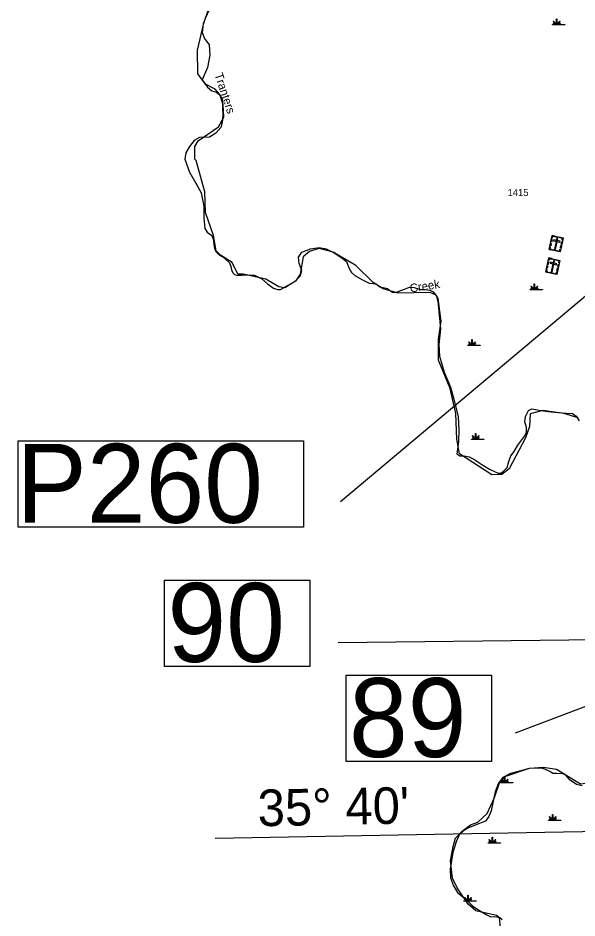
# Model space of a CAD drawing. Extents: x 2532689 to 2764727, y 536648 to 732970.
# Drawn here: x 2532689 to 2542603, y 701027 to 716987 of the extents above; entities that cross this region are included whole.
import ezdxf

# ---------------------------------------------------------------- set-up
doc = ezdxf.new("R2010")
doc.units = 0
for name, color, linetype in [('Exist Boundary Political CountyLine', 7, 'Continuous'), ('Exist Cultural Cemetery CELL', 7, 'Continuous'), ('Exist Hydrographic Creek Single Shore', 7, 'Continuous'), ('Exist Hydrographic Creek Single Shore Label', 7, 'Continuous'), ('Exist Hydrographic Swamp CELL', 7, 'Continuous'), ('Exist Road Secondary Structure Pipe Number Label', 7, 'Continuous'), ('Exist Road Secondary Structure Standard Bridge Number Label', 7, 'Continuous'), ('Exist Road Secondary Type 51 Number Label', 7, 'Continuous'), ('Map Preparation Longitude Latitude Label', 7, 'Continuous'), ('Map Preparation Longitude Latitude Lines', 7, 'Continuous')]:
    doc.layers.add(name, color=color, linetype=linetype)

msp = doc.modelspace()

# ---------------------------------------------------------------- linework, layer by layer
at = {"layer": 'Exist Boundary Political CountyLine'}
for points in [[(2536109, 717196), (2536014, 716987), (2535975, 716882), (2535955, 716728), (2535999, 716625), (2536079, 716511), (2536089, 716326), (2536049, 716112), (2535955, 715892)], [(2535955, 715892), (2536049, 715760), (2536129, 715695), (2536209, 715670), (2536274, 715620), (2536308, 715541), (2536318, 715406), (2536323, 715261), (2536308, 715132), (2536284, 715047), (2536199, 714942), (2536084, 714872), (2535905, 714870), (2535815, 714815), (2535730, 714710), (2535666, 714596), (2535646, 714486), (2535730, 714252), (2535840, 714057), (2535940, 713885), (2535985, 713651), (2535985, 713446), (2536004, 713254), (2536044, 713189), (2536129, 713130), (2536154, 713050), (2536164, 712970), (2536174, 712905), (2536199, 712845), (2536264, 712780), (2536343, 712736), (2536438, 712648), (2536463, 712578), (2536478, 712519), (2536498, 712469), (2536528, 712439), (2536578, 712429), (2536662, 712429), (2536797, 712434), (2536886, 712429), (2537011, 712359), (2537111, 712274), (2537220, 712194), (2537290, 712175), (2537345, 712172), (2537479, 712252), (2537604, 712322), (2537694, 712411), (2537724, 712511), (2537674, 712631), (2537664, 712743), (2537724, 712833), (2537878, 712893), (2538028, 712918), (2538152, 712893), (2538297, 712823), (2538441, 712728), (2538516, 712668), (2538556, 712559), (2538606, 712474), (2538665, 712419), (2538800, 712344), (2538915, 712282), (2539039, 712272), (2539109, 712222), (2539164, 712207), (2539244, 712192), (2539303, 712142), (2539333, 712127), (2539388, 712122), (2539458, 712147), (2539543, 712177), (2539632, 712212), (2539717, 712207), (2539792, 712187), (2539847, 712172), (2539911, 712172), (2539991, 712162), (2540051, 712132), (2540111, 712057), (2540136, 711963), (2540141, 711908), (2540180, 711476), (2540150, 711197), (2540165, 710988), (2540250, 710706), (2540360, 710442), (2540420, 710227), (2540494, 709913), (2540509, 709686), (2540499, 709472), (2540474, 709257), (2540524, 709222), (2540604, 709222), (2540689, 709207), (2540773, 709162), (2540913, 709068), (2541052, 708988), (2541207, 708913), (2541252, 708918), (2541302, 708953)], [(2541302, 708953), (2541366, 709018), (2541396, 709123), (2541431, 709222), (2541486, 709302), (2541551, 709412), (2541626, 709507), (2541680, 709576), (2541705, 709641), (2541705, 709731), (2541680, 709821), (2541690, 709920), (2541745, 710025), (2541800, 710058), (2541969, 710028), (2542084, 710008), (2542268, 709993), (2542418, 709978), (2542522, 709973), (2542587, 709925), (2542642, 709846)], [(2542592, 703393), (2542483, 703472), (2542403, 703557), (2542353, 703582), (2542243, 703592), (2542174, 703587), (2542124, 703627), (2542034, 703667), (2541969, 703682), (2541860, 703682), (2541755, 703677), (2541586, 703632), (2541426, 703587), (2541287, 703517), (2541212, 703418), (2541152, 703263), (2541117, 703098), (2541082, 702929), (2541042, 702829), (2540978, 702744), (2540798, 702674), (2540664, 702620), (2540589, 702575), (2540514, 702500), (2540459, 702380), (2540400, 702186), (2540355, 701892), (2540360, 701742), (2540410, 701597), (2540484, 701478), (2540644, 701348), (2540758, 701238), (2540873, 701158), (2540993, 701091), (2541072, 701046), (2541147, 701051), (2541237, 701036), (2541277, 701001)], [(2542692, 703370), (2542592, 703393)]]:
    msp.add_lwpolyline(points, dxfattribs=at)
at = {"layer": 'Exist Cultural Cemetery CELL'}
for points in [[(2542165, 713131), (2542359, 713087), (2542304, 712839), (2542109, 712882)], [(2542156, 713088), (2542167, 713086), (2542174, 713117), (2542213, 713109), (2542216, 713119), (2542165, 713131)], [(2542237, 713115), (2542288, 713103), (2542285, 713092), (2542235, 713103)], [(2542350, 713045), (2542339, 713047), (2542346, 713079), (2542306, 713088), (2542309, 713098), (2542359, 713087)], [(2542125, 712950), (2542134, 712993), (2542145, 712990), (2542136, 712948)], [(2542139, 713016), (2542149, 713058), (2542160, 713056), (2542150, 713014)], [(2542190, 713055), (2542186, 713037), (2542301, 713011), (2542305, 713030)], [(2542265, 713078), (2542247, 713082), (2542203, 712884), (2542221, 712880)], [(2542308, 712912), (2542318, 712954), (2542329, 712952), (2542320, 712909)], [(2542323, 712976), (2542332, 713018), (2542343, 713016), (2542334, 712974)], [(2542142, 712875), (2542144, 712886), (2542123, 712891), (2542132, 712931), (2542121, 712933), (2542109, 712882)], [(2542168, 712881), (2542251, 712862), (2542248, 712851), (2542166, 712870)], [(2542271, 712846), (2542274, 712857), (2542295, 712852), (2542304, 712892), (2542315, 712889), (2542304, 712839)], [(2542104, 712731), (2542299, 712687), (2542243, 712439), (2542049, 712482)], [(2542079, 712616), (2542088, 712659), (2542099, 712656), (2542090, 712614)], [(2542095, 712689), (2542106, 712686), (2542113, 712718), (2542153, 712709), (2542155, 712720), (2542104, 712731)], [(2542129, 712656), (2542125, 712637), (2542240, 712612), (2542244, 712630)], [(2542204, 712679), (2542186, 712683), (2542142, 712485), (2542160, 712481)], [(2542177, 712715), (2542227, 712703), (2542225, 712692), (2542174, 712704)], [(2542289, 712645), (2542278, 712648), (2542285, 712679), (2542246, 712688), (2542248, 712699), (2542299, 712687)], [(2542081, 712475), (2542083, 712487), (2542062, 712491), (2542071, 712531), (2542060, 712533), (2542049, 712483)], [(2542064, 712551), (2542073, 712593), (2542085, 712591), (2542075, 712548)], [(2542107, 712481), (2542190, 712463), (2542188, 712451), (2542105, 712470)], [(2542211, 712446), (2542213, 712457), (2542235, 712453), (2542243, 712492), (2542254, 712490), (2542243, 712439)], [(2542248, 712512), (2542257, 712554), (2542268, 712552), (2542259, 712509)], [(2542262, 712576), (2542272, 712619), (2542283, 712616), (2542273, 712574)]]:
    msp.add_lwpolyline(points, close=True, dxfattribs=at)
at = {"layer": 'Exist Hydrographic Creek Single Shore'}
for points in [[(2536585, 712446), (2536490, 712652), (2536279, 712781), (2536202, 712857), (2536156, 713131), (2536015, 713536), (2536000, 713903), (2535848, 714458), (2535823, 714483), (2535827, 714707), (2535883, 714807), (2536246, 715055), (2536342, 715227), (2536330, 715449), (2536268, 715631), (2536183, 715722), (2536015, 715811), (2535878, 715999), (2535871, 716416), (2535987, 716893), (2536074, 717153)], [(2542623, 709897), (2542372, 709976), (2541996, 710029), (2541772, 709968), (2541759, 709741), (2541688, 709541), (2541398, 708994), (2541267, 708890), (2541092, 708886), (2540518, 709260), (2540472, 709518), (2540455, 709976), (2540355, 710416), (2540146, 710919), (2540148, 711294), (2540192, 711611), (2540143, 712012), (2540108, 712070), (2539999, 712118), (2539433, 712105), (2539165, 712186), (2538988, 712297), (2538682, 712600), (2538278, 712836), (2538027, 712898), (2537861, 712846), (2537746, 712752), (2537693, 712442), (2537612, 712323), (2537423, 712204), (2537314, 712219), (2537087, 712355), (2536685, 712447), (2536585, 712446)], [(2540714, 702679), (2540846, 702724), (2541010, 702878), (2541138, 703163), (2541233, 703439), (2541339, 703542), (2541762, 703683), (2542003, 703703), (2542237, 703667), (2542667, 703408), (2542908, 703438), (2543220, 703693), (2543385, 703769), (2543949, 703913), (2544031, 703999), (2544061, 704167)], [(2541266, 700699), (2541227, 701032), (2541176, 701073), (2540808, 701156), (2540672, 701272), (2540476, 701560), (2540397, 701734), (2540359, 702041), (2540404, 702292), (2540451, 702442), (2540566, 702568), (2540714, 702679)]]:
    msp.add_lwpolyline(points, dxfattribs=at)
at = {"layer": 'Exist Hydrographic Swamp CELL'}
for points in [[(2542169, 716871), (2542222, 716871), (2542224, 716875), (2542186, 716890), (2542189, 716895), (2542226, 716879), (2542228, 716882), (2542183, 716927), (2542189, 716932), (2542234, 716886), (2542240, 716889), (2542240, 716972), (2542247, 716972), (2542247, 716889), (2542254, 716886), (2542299, 716932), (2542304, 716927), (2542260, 716882), (2542262, 716878), (2542303, 716897), (2542305, 716892), (2542264, 716874), (2542266, 716871), (2542387, 716871), (2542387, 716864), (2542169, 716864)], [(2541772, 712171), (2541825, 712172), (2541827, 712175), (2541789, 712190), (2541791, 712195), (2541829, 712179), (2541831, 712182), (2541786, 712227), (2541791, 712232), (2541837, 712187), (2541843, 712189), (2541843, 712272), (2541850, 712272), (2541850, 712189), (2541857, 712187), (2541902, 712232), (2541907, 712227), (2541863, 712182), (2541865, 712179), (2541906, 712197), (2541908, 712192), (2541867, 712174), (2541869, 712172), (2541990, 712171), (2541990, 712164), (2541772, 712164)], [(2540667, 711187), (2540720, 711187), (2540722, 711190), (2540684, 711205), (2540686, 711210), (2540724, 711195), (2540726, 711197), (2540681, 711242), (2540687, 711247), (2540732, 711202), (2540738, 711204), (2540738, 711287), (2540745, 711287), (2540745, 711204), (2540752, 711202), (2540797, 711247), (2540802, 711242), (2540758, 711197), (2540760, 711194), (2540801, 711212), (2540803, 711207), (2540762, 711190), (2540764, 711187), (2540885, 711187), (2540885, 711180), (2540667, 711180)], [(2540730, 709521), (2540783, 709521), (2540785, 709524), (2540747, 709539), (2540750, 709544), (2540787, 709529), (2540789, 709532), (2540745, 709576), (2540750, 709581), (2540795, 709536), (2540801, 709538), (2540801, 709621), (2540809, 709621), (2540809, 709538), (2540815, 709536), (2540860, 709581), (2540865, 709576), (2540821, 709532), (2540823, 709528), (2540864, 709547), (2540866, 709542), (2540825, 709524), (2540827, 709521), (2540948, 709521), (2540948, 709514), (2540730, 709514)], [(2541245, 703430), (2541298, 703430), (2541300, 703433), (2541262, 703448), (2541265, 703453), (2541302, 703438), (2541304, 703441), (2541259, 703485), (2541265, 703490), (2541310, 703445), (2541316, 703447), (2541316, 703530), (2541323, 703530), (2541323, 703447), (2541330, 703445), (2541375, 703490), (2541380, 703485), (2541336, 703441), (2541338, 703437), (2541379, 703456), (2541381, 703450), (2541340, 703433), (2541342, 703430), (2541463, 703430), (2541463, 703423), (2541245, 703423)], [(2542099, 702764), (2542151, 702764), (2542153, 702768), (2542115, 702782), (2542118, 702788), (2542156, 702772), (2542157, 702775), (2542113, 702819), (2542118, 702824), (2542163, 702779), (2542170, 702781), (2542170, 702864), (2542177, 702864), (2542177, 702781), (2542183, 702779), (2542228, 702824), (2542233, 702819), (2542189, 702775), (2542191, 702771), (2542232, 702790), (2542234, 702785), (2542193, 702767), (2542195, 702764), (2542316, 702764), (2542316, 702757), (2542099, 702757)], [(2541028, 702359), (2541081, 702359), (2541083, 702362), (2541045, 702377), (2541048, 702382), (2541085, 702367), (2541087, 702369), (2541042, 702414), (2541048, 702419), (2541093, 702374), (2541099, 702376), (2541099, 702459), (2541106, 702459), (2541106, 702376), (2541113, 702374), (2541158, 702419), (2541163, 702414), (2541119, 702369), (2541121, 702366), (2541162, 702384), (2541164, 702379), (2541123, 702362), (2541125, 702359), (2541246, 702359), (2541246, 702351), (2541028, 702351)], [(2540594, 701331), (2540647, 701331), (2540649, 701335), (2540611, 701349), (2540614, 701355), (2540651, 701339), (2540653, 701342), (2540609, 701386), (2540614, 701391), (2540659, 701346), (2540665, 701348), (2540665, 701431), (2540673, 701431), (2540673, 701348), (2540679, 701346), (2540724, 701391), (2540729, 701386), (2540685, 701342), (2540687, 701338), (2540728, 701357), (2540730, 701352), (2540689, 701334), (2540691, 701331), (2540812, 701331), (2540812, 701324), (2540594, 701324)]]:
    msp.add_lwpolyline(points, close=True, dxfattribs=at)
at = {"layer": 'Exist Road Secondary Structure Pipe Number Label'}
msp.add_line((2543094, 712341), (2538408, 708407), dxfattribs=at)
msp.add_lwpolyline([(2532689, 709491), (2537753, 709491), (2537753, 707955), (2532689, 707955)], close=True, dxfattribs=at)
at = {"layer": 'Exist Road Secondary Structure Standard Bridge Number Label'}
for p, q in [((2546489, 706190), (2541505, 704305)), ((2542983, 705962), (2538367, 705909))]:
    msp.add_line(p, q, dxfattribs=at)
for points in [[(2535290, 707018), (2537866, 707018), (2537866, 705489), (2535290, 705489)], [(2538510, 705331), (2541087, 705331), (2541087, 703801), (2538510, 703801)]]:
    msp.add_lwpolyline(points, close=True, dxfattribs=at)
at = {"layer": 'Map Preparation Longitude Latitude Lines'}
msp.add_lwpolyline([(2536183, 702443), (2542030, 702548), (2547688, 702650)], dxfattribs=at)

# ---------------------------------------------------------------- texts
at = {"layer": 'Exist Hydrographic Creek Single Shore Label'}
for s, rotation, p in [('Tranters', 288.2714, (2536172, 715985)), ('Creek', 8.9715, (2539650, 712117))]:
    msp.add_text(s, height=150, rotation=rotation, dxfattribs=at).set_placement(p)
at = {"layer": 'Exist Road Secondary Structure Pipe Number Label'}
msp.add_text('P260', height=1400, dxfattribs=at).set_placement((2532660, 708035))
at = {"layer": 'Exist Road Secondary Structure Standard Bridge Number Label'}
for s, p in [('90', (2535340, 705568)), ('89', (2538560, 703881))]:
    msp.add_text(s, height=1400, dxfattribs=at).set_placement(p)
at = {"layer": 'Exist Road Secondary Type 51 Number Label'}
msp.add_text('1415', height=125, dxfattribs=at).set_placement((2541371, 713829))
at = {"layer": 'Map Preparation Longitude Latitude Label'}
msp.add_text("35° 40'", height=650, rotation=1.0341, dxfattribs=at).set_placement((2536945, 702653))

doc.saveas('drawing.dxf')
